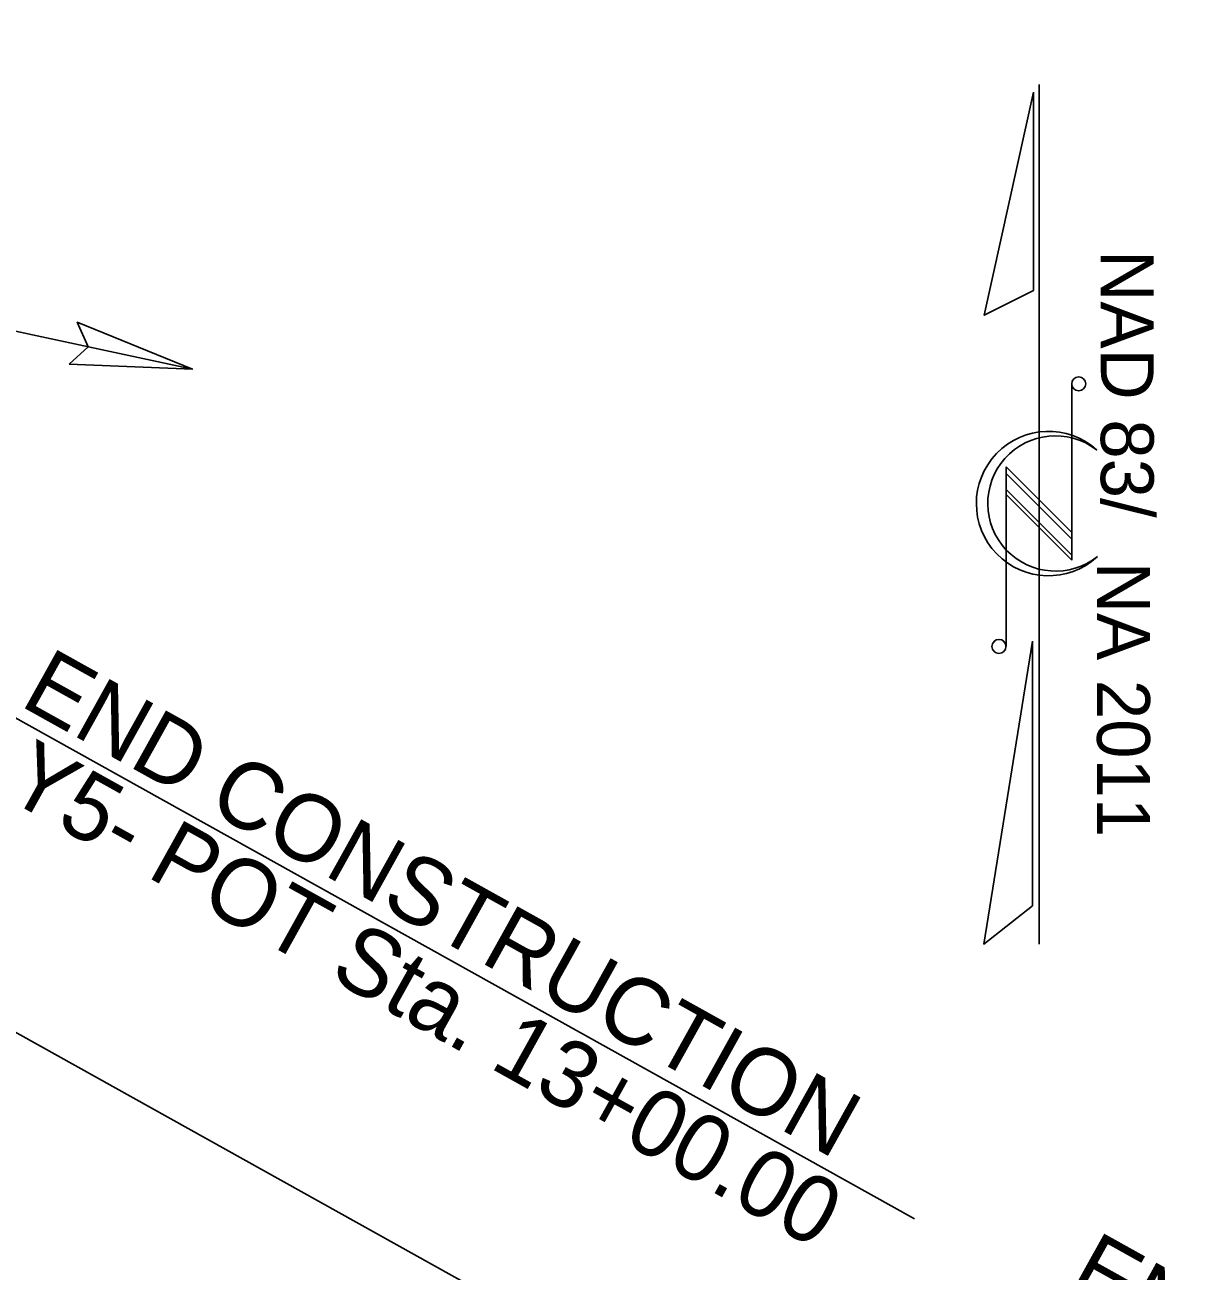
# Model space of a CAD drawing. Extents: x 1754939 to 1770240, y 706534 to 717510.
# Drawn here: x 1764774 to 1765886, y 711317 to 712504 of the extents above; entities that cross this region are included whole.
import ezdxf

# ---------------------------------------------------------------- set-up
doc = ezdxf.new("R2010")
doc.units = 0
for name, color, linetype in [('ENG SEALS CELL', 7, 'Continuous'), ('Prop Guardrail Anchor Unit CELL', 7, 'Continuous'), ('Prop Roadway Culvert', 7, 'Continuous'), ('Prop SS Cut Line', 7, 'Continuous'), ('Scratch_Level_3', 7, 'Continuous'), ('Sheet PE Seal Cell', 7, 'Continuous')]:
    doc.layers.add(name, color=color, linetype=linetype)

msp = doc.modelspace()

# ---------------------------------------------------------------- linework, layer by layer
at = {"layer": 'ENG SEALS CELL'}
msp.add_lwpolyline([(1763634.2, 710972.3), (1763634.2, 710972.3), (1763865.7, 711388), (1764374.3, 711762), (1765360.9, 711212.6), (1765258, 711027.8), (1764850.1, 710295.2)], close=True, dxfattribs=at)
at = {"layer": 'Prop Guardrail Anchor Unit CELL'}
msp.add_lwpolyline([(1764816.3, 712181.1), (1764934, 712176.2), (1764824.2, 712220.9), (1764834.4, 712197.6)], close=True, dxfattribs=at)
at = {"layer": 'Prop Roadway Culvert'}
for p, q in [((1765741.4, 711628.4), (1765741.4, 712447.4)), ((1765772.3, 712162.4), (1765772.3, 711994.3)), ((1765795.5, 712099.7), (1765796.4, 712099.1)), ((1765772.3, 712020.5), (1765709.7, 712083.1)), ((1765709.7, 712083.1), (1765709.7, 711912.3)), ((1765772.3, 712014.3), (1765709.7, 712076.9)), ((1765709.7, 712076.9), (1765709.7, 712061.6)), ((1765772.3, 711998.9), (1765709.7, 712061.6)), ((1765709.7, 712061.6), (1765772.3, 711998.9)), ((1765772.3, 711994.3), (1765709.7, 712056.9)), ((1765772.3, 711998.9), (1765772.3, 712014.3))]:
    msp.add_line(p, q, dxfattribs=at)
for points in [[(1765735.8, 712440.2), (1765689, 712227.5), (1765735.8, 712251.2)], [(1765734.8, 711916.9), (1765688.4, 711628.4), (1765734.8, 711664.9)]]:
    msp.add_lwpolyline(points, close=True, dxfattribs=at)
for centre in [(1765779, 712162.2), (1765703, 711912)]:
    msp.add_circle(centre, 6.68, dxfattribs=at)
for centre, radius, start, end in [((1765750.2, 712048.1), 68.8, 47.84, 312.3941), ((1765756.8, 712048.2), 64.5, 53.095, 308.6287)]:
    msp.add_arc(centre, radius, start, end, dxfattribs=at)
at = {"layer": 'Prop SS Cut Line'}
msp.add_line((1764759, 711847.3), (1765622.5, 711366.4), dxfattribs=at)
at = {"layer": 'Sheet PE Seal Cell'}
msp.add_line((1764934, 712176.2), (1764488.8, 712271.9), dxfattribs=at)

# ---------------------------------------------------------------- texts
at = {"layer": 'Prop Roadway Culvert'}
for s, p in [('NAD 83/', (1765800.1, 712289.4)), ('NA 2011', (1765796.5, 711992.5))]:
    msp.add_text(s, height=50.4, rotation=270, dxfattribs=at).set_placement(p)
at = {"layer": 'Prop SS Cut Line'}
for s, p in [('END CONSTRUCTION', (1764768.1, 711856.3)), ('-Y5- POT Sta. 13+00.00', (1764727.5, 711783.2)), ('END CONSTRUCTION', (1765766.2, 711300.1))]:
    msp.add_text(s, height=63.75, rotation=330.8875, dxfattribs=at).set_placement(p)
at = {"layer": 'Scratch_Level_3'}
msp.add_text('DRAINAGE, GRADING, PAVING, SIGNALS AND CULVERTS', height=75.001, rotation=330.8875, dxfattribs=at).set_placement((1764991.8, 713646.3))

doc.saveas('drawing.dxf')
